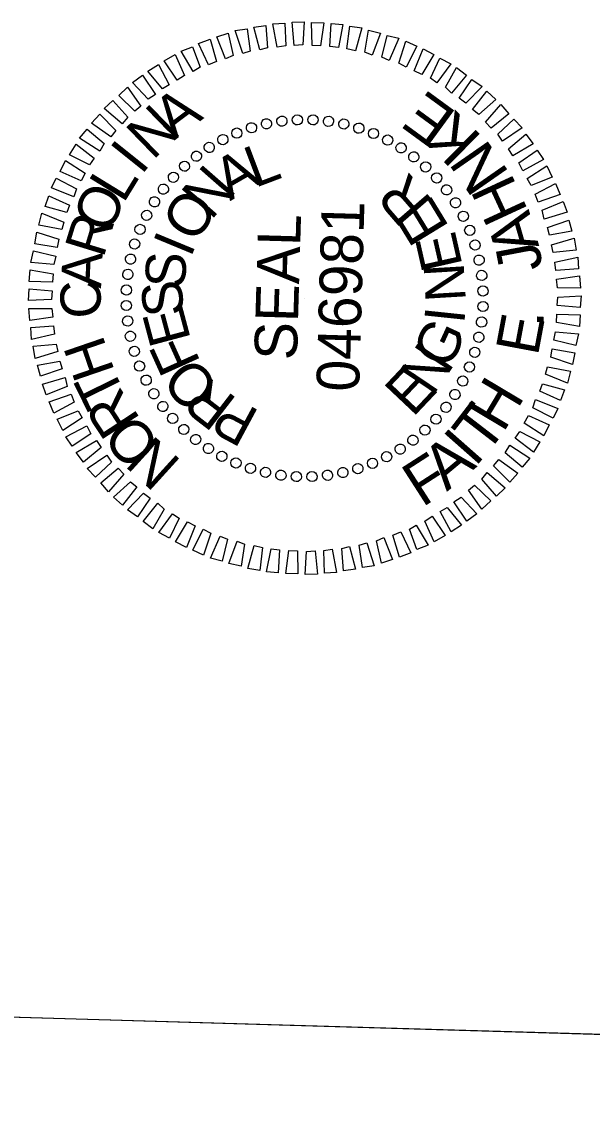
# Model space of a CAD drawing. Extents: x 2097002 to 2098146, y 685127 to 687089.
# Drawn here: x 2097162.3 to 2097242.5, y 686598.1 to 686752 of the extents above; entities that cross this region are included whole.
import ezdxf

# ---------------------------------------------------------------- set-up
doc = ezdxf.new("R2010")
doc.units = 0
for name, color, linetype in [('Default', 7, 'Continuous'), ('Sheet Layout Plan Border', 7, 'Continuous'), ('Sheet Title CELL', 7, 'Continuous')]:
    doc.layers.add(name, color=color, linetype=linetype)

msp = doc.modelspace()

# ---------------------------------------------------------------- linework, layer by layer
at = {"layer": 'Default'}
for p, q in [((2097194.58, 686737.11), (2097194.58, 686737.11)), ((2097196.69, 686737.65), (2097196.69, 686737.65)), ((2097198.9, 686737.99), (2097198.9, 686737.99)), ((2097201.06, 686738.23), (2097201.06, 686738.23)), ((2097203.26, 686738.21), (2097203.26, 686738.21)), ((2097205.46, 686738), (2097205.46, 686738)), ((2097207.59, 686737.59), (2097207.59, 686737.59)), ((2097209.68, 686737.08), (2097209.68, 686737.08)), ((2097190.58, 686735.43), (2097190.58, 686735.43)), ((2097192.55, 686736.37), (2097192.55, 686736.37)), ((2097211.76, 686736.31), (2097211.76, 686736.31)), ((2097213.73, 686735.36), (2097213.73, 686735.36)), ((2097188.64, 686734.34), (2097188.64, 686734.34)), ((2097215.65, 686734.3), (2097215.65, 686734.3)), ((2097186.86, 686733.14), (2097186.86, 686733.14)), ((2097217.42, 686733), (2097217.42, 686733)), ((2097185.16, 686731.69), (2097185.16, 686731.69)), ((2097219.13, 686731.6), (2097219.13, 686731.6)), ((2097183.62, 686730.18), (2097183.62, 686730.18)), ((2097220.63, 686730.05), (2097220.63, 686730.05)), ((2097182.22, 686728.47), (2097182.22, 686728.47)), ((2097222.08, 686728.36), (2097222.08, 686728.36)), ((2097180.92, 686726.71), (2097180.92, 686726.71)), ((2097223.28, 686726.58), (2097223.28, 686726.58)), ((2097179.86, 686724.79), (2097179.86, 686724.79)), ((2097224.38, 686724.64), (2097224.38, 686724.64)), ((2097178.9, 686722.81), (2097178.9, 686722.81)), ((2097225.32, 686722.66), (2097225.32, 686722.66)), ((2097178.14, 686720.73), (2097178.14, 686720.73)), ((2097226.06, 686720.64), (2097226.06, 686720.64)), ((2097177.63, 686718.65), (2097177.63, 686718.65)), ((2097226.6, 686718.53), (2097226.6, 686718.53)), ((2097177.22, 686716.51), (2097177.22, 686716.51)), ((2097226.93, 686716.31), (2097226.93, 686716.31)), ((2097177.01, 686714.31), (2097177.01, 686714.31)), ((2097227.17, 686714.16), (2097227.17, 686714.16)), ((2097202.08, 686713.14), (2097202.08, 686713.14)), ((2097176.99, 686712.11), (2097176.99, 686712.11)), ((2097227.16, 686711.96), (2097227.16, 686711.96)), ((2097177.23, 686709.96), (2097177.23, 686709.96)), ((2097226.94, 686709.76), (2097226.94, 686709.76)), ((2097177.57, 686707.75), (2097177.57, 686707.75)), ((2097226.53, 686707.62), (2097226.53, 686707.62)), ((2097178.1, 686705.63), (2097178.1, 686705.63)), ((2097226.02, 686705.54), (2097226.02, 686705.54)), ((2097178.85, 686703.61), (2097178.85, 686703.61)), ((2097225.26, 686703.46), (2097225.26, 686703.46)), ((2097179.79, 686701.63), (2097179.79, 686701.63)), ((2097224.3, 686701.49), (2097224.3, 686701.49)), ((2097180.88, 686699.7), (2097180.88, 686699.7)), ((2097223.25, 686699.57), (2097223.25, 686699.57)), ((2097182.08, 686697.91), (2097182.08, 686697.91)), ((2097221.94, 686697.8), (2097221.94, 686697.8)), ((2097183.53, 686696.22), (2097183.53, 686696.22)), ((2097220.54, 686696.09), (2097220.54, 686696.09)), ((2097185.04, 686694.67), (2097185.04, 686694.67)), ((2097219, 686694.59), (2097219, 686694.59)), ((2097186.75, 686693.27), (2097186.75, 686693.27)), ((2097217.31, 686693.13), (2097217.31, 686693.13)), ((2097188.51, 686691.97), (2097188.51, 686691.97)), ((2097190.43, 686690.91), (2097190.43, 686690.91)), ((2097213.59, 686690.84), (2097213.59, 686690.84)), ((2097215.52, 686691.94), (2097215.52, 686691.94)), ((2097192.4, 686689.96), (2097192.4, 686689.96)), ((2097194.48, 686689.2), (2097194.48, 686689.2)), ((2097209.59, 686689.16), (2097209.59, 686689.16)), ((2097211.61, 686689.9), (2097211.61, 686689.9)), ((2097196.57, 686688.69), (2097196.57, 686688.69)), ((2097198.71, 686688.27), (2097198.71, 686688.27)), ((2097200.9, 686688.06), (2097200.9, 686688.06)), ((2097203.1, 686688.05), (2097203.1, 686688.05)), ((2097205.26, 686688.28), (2097205.26, 686688.28)), ((2097207.47, 686688.62), (2097207.47, 686688.62))]:
    msp.add_line(p, q, dxfattribs=at)
for points in [[(2097193.38, 686747.5), (2097192.32, 686750.74), (2097193.98, 686750.99), (2097194.44, 686747.82)], [(2097195.79, 686748.03), (2097194.94, 686751.21), (2097196.64, 686751.46), (2097196.85, 686748.3)], [(2097198.21, 686748.41), (2097197.6, 686751.68), (2097199.3, 686751.78), (2097199.41, 686748.58)], [(2097200.61, 686748.64), (2097200.31, 686751.9), (2097202.01, 686751.95), (2097201.82, 686748.71)], [(2097203.11, 686748.62), (2097203.06, 686751.87), (2097204.76, 686751.82), (2097204.31, 686748.59)], [(2097205.61, 686748.5), (2097205.81, 686751.74), (2097207.45, 686751.6), (2097206.81, 686748.36)], [(2097208, 686748.18), (2097208.4, 686751.37), (2097210.09, 686751.12), (2097209.2, 686747.89)], [(2097210.54, 686747.7), (2097211.03, 686750.79), (2097212.72, 686750.39), (2097211.58, 686747.27)], [(2097188.58, 686745.94), (2097187.17, 686748.93), (2097188.78, 686749.54), (2097189.69, 686746.41)], [(2097190.95, 686746.77), (2097189.74, 686749.86), (2097191.31, 686750.36), (2097192.02, 686747.24)], [(2097212.92, 686746.99), (2097213.66, 686750.06), (2097215.3, 686749.67), (2097213.96, 686746.55)], [(2097215.3, 686746.17), (2097216.29, 686749.24), (2097217.82, 686748.54), (2097216.33, 686745.59)], [(2097186.4, 686745), (2097184.73, 686747.85), (2097186.3, 686748.46), (2097187.37, 686745.58)], [(2097217.47, 686745.1), (2097218.71, 686748.17), (2097220.23, 686747.37), (2097218.55, 686744.57)], [(2097184.16, 686743.77), (2097182.34, 686746.47), (2097183.87, 686747.38), (2097185.18, 686744.44)], [(2097219.74, 686744.04), (2097221.07, 686746.85), (2097222.6, 686746.05), (2097220.67, 686743.41)], [(2097182.08, 686742.53), (2097180.05, 686745.04), (2097181.53, 686745.95), (2097183.04, 686743.1)], [(2097221.85, 686742.77), (2097223.43, 686745.53), (2097224.8, 686744.49), (2097222.73, 686741.95)], [(2097180.09, 686741.09), (2097177.9, 686743.45), (2097179.28, 686744.46), (2097181.1, 686741.76)], [(2097223.81, 686741.22), (2097225.58, 686743.87), (2097227.01, 686742.87), (2097224.74, 686740.54)], [(2097178.23, 686739.39), (2097175.95, 686741.61), (2097177.18, 686742.77), (2097179.06, 686740.12)], [(2097225.66, 686739.66), (2097227.69, 686742.2), (2097228.96, 686741.07), (2097226.54, 686738.94)], [(2097176.43, 686737.64), (2097173.89, 686739.77), (2097175.13, 686740.93), (2097177.21, 686738.57)], [(2097227.51, 686737.86), (2097229.63, 686740.35), (2097230.75, 686739.06), (2097228.29, 686737.03)], [(2097174.83, 686735.79), (2097172.13, 686737.72), (2097173.27, 686738.98), (2097175.56, 686736.72)], [(2097173.27, 686733.78), (2097170.42, 686735.62), (2097171.51, 686736.88), (2097173.9, 686734.86)], [(2097229.21, 686736.16), (2097231.48, 686738.29), (2097232.64, 686737.06), (2097229.88, 686735.19)], [(2097230.7, 686734.11), (2097233.17, 686736.19), (2097234.18, 686734.81), (2097231.33, 686733.14)], [(2097171.86, 686731.87), (2097169.05, 686733.3), (2097169.95, 686734.78), (2097172.49, 686732.8)], [(2097232.15, 686732.17), (2097234.75, 686733.95), (2097235.66, 686732.62), (2097232.72, 686731.05)], [(2097170.65, 686729.61), (2097167.73, 686730.94), (2097168.48, 686732.47), (2097171.23, 686730.69)], [(2097233.33, 686729.93), (2097236.09, 686731.71), (2097236.84, 686730.13), (2097233.91, 686728.97)], [(2097169.63, 686727.38), (2097166.52, 686728.63), (2097167.16, 686730.01), (2097170.02, 686728.52)], [(2097234.47, 686727.75), (2097237.32, 686729.27), (2097237.97, 686727.7), (2097234.89, 686726.64)], [(2097168.67, 686725.16), (2097165.59, 686726), (2097166.14, 686727.54), (2097169.05, 686726.2)], [(2097235.46, 686725.52), (2097238.39, 686726.74), (2097238.95, 686725.22), (2097235.72, 686724.26)], [(2097167.95, 686722.78), (2097164.71, 686723.38), (2097165.16, 686725.06), (2097168.23, 686723.82)], [(2097236.18, 686723.05), (2097239.22, 686724.11), (2097239.62, 686722.55), (2097236.5, 686721.99)], [(2097167.32, 686720.25), (2097164.14, 686720.79), (2097164.44, 686722.43), (2097167.51, 686721.44)], [(2097236.76, 686720.63), (2097239.94, 686721.59), (2097240.24, 686719.88), (2097236.98, 686719.57)], [(2097166.85, 686717.86), (2097163.61, 686718.16), (2097163.96, 686719.8), (2097167.09, 686719.06)], [(2097237.24, 686718.22), (2097240.47, 686718.92), (2097240.57, 686717.27), (2097237.36, 686717.01)], [(2097166.63, 686715.37), (2097163.38, 686715.46), (2097163.48, 686717.11), (2097166.72, 686716.56)], [(2097237.47, 686715.81), (2097240.69, 686716.27), (2097240.84, 686714.56), (2097237.59, 686714.6)], [(2097166.51, 686712.97), (2097163.26, 686712.81), (2097163.35, 686714.46), (2097166.6, 686714.17)], [(2097237.65, 686713.3), (2097240.91, 686713.46), (2097240.81, 686711.81), (2097237.57, 686712.1)], [(2097166.69, 686710.46), (2097163.47, 686710.01), (2097163.32, 686711.71), (2097166.57, 686711.67)], [(2097237.53, 686710.9), (2097240.78, 686710.81), (2097240.68, 686709.16), (2097237.45, 686709.71)], [(2097166.92, 686708.06), (2097163.7, 686707.35), (2097163.6, 686709), (2097166.8, 686709.26)], [(2097237.31, 686708.41), (2097240.55, 686708.12), (2097240.2, 686706.48), (2097237.07, 686707.22)], [(2097167.4, 686705.64), (2097164.22, 686704.68), (2097163.92, 686706.39), (2097167.18, 686706.7)], [(2097236.84, 686706.02), (2097240.03, 686705.48), (2097239.73, 686703.84), (2097236.66, 686704.83)], [(2097167.98, 686703.22), (2097164.95, 686702.16), (2097164.54, 686703.72), (2097167.66, 686704.28)], [(2097236.22, 686703.49), (2097239.45, 686702.9), (2097239, 686701.21), (2097235.94, 686702.45)], [(2097168.71, 686700.75), (2097165.77, 686699.54), (2097165.22, 686701.05), (2097168.44, 686702.01)], [(2097235.5, 686701.11), (2097238.57, 686700.27), (2097238.03, 686698.74), (2097235.12, 686700.07)], [(2097169.69, 686698.52), (2097166.85, 686697), (2097166.19, 686698.57), (2097169.28, 686699.63)], [(2097234.53, 686698.89), (2097237.65, 686697.65), (2097237.01, 686696.26), (2097234.15, 686697.75)], [(2097170.83, 686696.34), (2097168.08, 686694.57), (2097167.32, 686696.14), (2097170.26, 686697.3)], [(2097233.52, 686696.67), (2097236.43, 686695.33), (2097235.68, 686693.8), (2097232.94, 686695.58)], [(2097172.02, 686694.1), (2097169.41, 686692.33), (2097168.5, 686693.65), (2097171.45, 686695.22)], [(2097232.3, 686694.4), (2097235.11, 686692.97), (2097234.22, 686691.49), (2097231.67, 686693.47)], [(2097173.46, 686692.16), (2097171, 686690.08), (2097169.99, 686691.46), (2097172.84, 686693.13)], [(2097230.89, 686692.49), (2097233.74, 686690.66), (2097232.65, 686689.39), (2097230.26, 686691.41)], [(2097174.95, 686690.11), (2097172.69, 686687.98), (2097171.52, 686689.21), (2097174.28, 686691.08)], [(2097176.65, 686688.41), (2097174.53, 686685.92), (2097173.42, 686687.21), (2097175.88, 686689.24)], [(2097229.34, 686690.48), (2097232.03, 686688.56), (2097230.89, 686687.29), (2097228.61, 686689.56)], [(2097227.73, 686688.63), (2097230.27, 686686.51), (2097229.04, 686685.34), (2097226.95, 686687.7)], [(2097178.5, 686686.61), (2097176.48, 686684.07), (2097175.21, 686685.2), (2097177.62, 686687.34)], [(2097225.93, 686686.88), (2097228.22, 686684.66), (2097226.98, 686683.5), (2097225.11, 686686.16)], [(2097180.36, 686685.06), (2097178.58, 686682.41), (2097177.16, 686683.4), (2097179.43, 686685.73)], [(2097224.08, 686685.18), (2097226.26, 686682.82), (2097224.88, 686681.81), (2097223.06, 686684.51)], [(2097182.31, 686683.5), (2097180.73, 686680.74), (2097179.36, 686681.78), (2097181.44, 686684.32)], [(2097222.09, 686683.74), (2097224.11, 686681.23), (2097222.64, 686680.32), (2097221.12, 686683.17)], [(2097184.43, 686682.24), (2097183.09, 686679.42), (2097181.57, 686680.22), (2097183.49, 686682.86)], [(2097186.7, 686681.17), (2097185.46, 686678.1), (2097183.93, 686678.9), (2097185.61, 686681.7)], [(2097220, 686682.5), (2097221.82, 686679.8), (2097220.29, 686678.89), (2097218.98, 686681.83)], [(2097188.87, 686680.11), (2097187.88, 686677.03), (2097186.35, 686677.73), (2097187.83, 686680.69)], [(2097215.58, 686680.33), (2097217, 686677.34), (2097215.38, 686676.73), (2097214.47, 686679.86)], [(2097217.76, 686681.27), (2097219.43, 686678.42), (2097217.86, 686677.81), (2097216.8, 686680.69)], [(2097191.24, 686679.29), (2097190.5, 686676.21), (2097188.86, 686676.6), (2097190.21, 686679.72)], [(2097193.62, 686678.57), (2097193.13, 686675.48), (2097191.44, 686675.88), (2097192.59, 686679)], [(2097210.79, 686678.77), (2097211.84, 686675.54), (2097210.19, 686675.28), (2097209.73, 686678.45)], [(2097213.21, 686679.5), (2097214.42, 686676.41), (2097212.85, 686675.91), (2097212.15, 686679.03)], [(2097196.16, 686678.09), (2097195.77, 686674.9), (2097194.07, 686675.15), (2097194.97, 686678.38)], [(2097198.55, 686677.77), (2097198.36, 686674.53), (2097196.71, 686674.68), (2097197.36, 686677.91)], [(2097201.05, 686677.65), (2097201.11, 686674.4), (2097199.41, 686674.45), (2097199.85, 686677.69)], [(2097203.55, 686677.63), (2097203.86, 686674.37), (2097202.15, 686674.32), (2097202.35, 686677.56)], [(2097205.96, 686677.86), (2097206.56, 686674.59), (2097204.86, 686674.49), (2097204.75, 686677.69)], [(2097208.37, 686678.24), (2097209.23, 686675.06), (2097207.52, 686674.81), (2097207.31, 686677.97)]]:
    msp.add_lwpolyline(points, close=True, dxfattribs=at)
for centre, major_axis in [((2097196.72, 686737.64), (-0.154, 0.703)), ((2097198.88, 686738.01), (-0.092, 0.714)), ((2097201.06, 686738.19), (-0.029, 0.719)), ((2097203.25, 686738.19), (0.033, 0.719)), ((2097205.43, 686737.99), (0.096, 0.714)), ((2097207.58, 686737.61), (0.158, 0.702)), ((2097192.55, 686736.33), (-0.274, 0.666)), ((2097194.61, 686737.08), (-0.215, 0.687)), ((2097209.69, 686737.03), (0.218, 0.686)), ((2097211.75, 686736.28), (0.277, 0.664)), ((2097190.57, 686735.42), (-0.331, 0.64)), ((2097213.73, 686735.35), (0.334, 0.638)), ((2097186.87, 686733.08), (-0.437, 0.572)), ((2097188.67, 686734.33), (-0.385, 0.608)), ((2097215.62, 686734.25), (0.389, 0.606)), ((2097217.41, 686732.99), (0.44, 0.57)), ((2097185.19, 686731.68), (-0.485, 0.532)), ((2097219.08, 686731.58), (0.488, 0.529)), ((2097183.64, 686730.13), (-0.529, 0.488)), ((2097220.62, 686730.03), (0.532, 0.485)), ((2097182.23, 686728.46), (-0.57, 0.44)), ((2097222.02, 686728.35), (0.572, 0.437)), ((2097180.97, 686726.67), (-0.606, 0.389)), ((2097223.27, 686726.55), (0.608, 0.385)), ((2097179.87, 686724.78), (-0.638, 0.334)), ((2097224.36, 686724.65), (0.64, 0.331)), ((2097178.94, 686722.8), (-0.664, 0.277)), ((2097225.28, 686722.67), (0.666, 0.274)), ((2097178.18, 686720.75), (-0.686, 0.218)), ((2097226.02, 686720.61), (0.687, 0.215)), ((2097177.61, 686718.63), (-0.702, 0.158)), ((2097226.58, 686718.49), (0.703, 0.154)), ((2097177.23, 686716.48), (-0.714, 0.096)), ((2097226.96, 686716.34), (0.714, 0.092)), ((2097177.03, 686714.3), (-0.719, 0.033)), ((2097227.14, 686714.16), (0.719, 0.029)), ((2097177.02, 686712.11), (-0.719, -0.029)), ((2097227.13, 686711.97), (0.719, -0.033)), ((2097177.21, 686709.93), (-0.714, -0.092)), ((2097226.94, 686709.79), (0.714, -0.096)), ((2097177.58, 686707.78), (-0.703, -0.154)), ((2097226.55, 686707.64), (0.702, -0.158)), ((2097178.14, 686705.66), (-0.687, -0.215)), ((2097225.98, 686705.53), (0.686, -0.218)), ((2097178.88, 686703.6), (-0.666, -0.274)), ((2097225.23, 686703.47), (0.664, -0.277)), ((2097179.8, 686701.62), (-0.64, -0.331)), ((2097224.29, 686701.49), (0.638, -0.334)), ((2097180.89, 686699.72), (-0.608, -0.385)), ((2097223.2, 686699.6), (0.606, -0.389)), ((2097182.14, 686697.93), (-0.572, -0.437)), ((2097221.94, 686697.81), (0.57, -0.44)), ((2097183.54, 686696.25), (-0.532, -0.485)), ((2097220.52, 686696.14), (0.529, -0.488)), ((2097185.09, 686694.69), (-0.488, -0.529)), ((2097218.97, 686694.6), (0.485, -0.532)), ((2097186.76, 686693.28), (-0.44, -0.57)), ((2097217.29, 686693.19), (0.437, -0.572)), ((2097188.55, 686692.02), (-0.389, -0.606)), ((2097215.5, 686691.94), (0.385, -0.608)), ((2097190.44, 686690.92), (-0.334, -0.638)), ((2097192.42, 686689.99), (-0.277, -0.664)), ((2097211.61, 686689.94), (0.274, -0.666)), ((2097213.6, 686690.86), (0.331, -0.64)), ((2097194.47, 686689.24), (-0.218, -0.686)), ((2097196.58, 686688.67), (-0.158, -0.702)), ((2097207.44, 686688.63), (0.154, -0.703)), ((2097209.55, 686689.19), (0.215, -0.687)), ((2097198.74, 686688.28), (-0.096, -0.714)), ((2097200.92, 686688.08), (-0.033, -0.719)), ((2097203.1, 686688.08), (0.029, -0.719)), ((2097205.28, 686688.26), (0.092, -0.714))]:
    msp.add_ellipse(centre, major_axis=major_axis, ratio=0.999708, dxfattribs=at)
at = {"layer": 'Sheet Layout Plan Border'}
msp.add_lwpolyline([(2098110.68, 686386.52), (2098090.85, 685704.42), (2097236.93, 685318.96), (2097029.37, 685324.99), (2097061.33, 686424.42), (2097062.77, 686473.85), (2097066.87, 686614.87), (2097306.86, 686607.89), (2097310.43, 686730.69), (2098032.53, 686709.7), (2098023.21, 686389.06)], close=True, dxfattribs=at)
at = {"layer": 'Sheet Title CELL'}
msp.add_line((2097066.87, 686614.87), (2097256.01, 686609.37), dxfattribs=at)

# ---------------------------------------------------------------- texts
at = {"layer": 'Default'}
for s, height, rotation, p in [('A', 5.95, 36.952, (2097183.77, 686735.28)), ('E', 6.29, 143.8279, (2097223.64, 686739.12)), ('N', 5.99, 44.1537, (2097180.73, 686732.41)), ('K', 6.36, 135.5439, (2097227.16, 686735.75)), ('I', 5.98, 51.355, (2097179.12, 686730.31)), ('L', 5.79, 20.7357, (2097195.08, 686728.6)), ('N', 6.36, 124.8181, (2097230.93, 686730.68)), ('A', 5.89, 30.0951, (2097191.57, 686726.75)), ('N', 5.99, 48.8114, (2097188.89, 686723.97)), ('R', 5.99, 130.8162, (2097220.23, 686726.71)), ('L', 5.93, 58.5557, (2097176.6, 686726.33)), ('H', 6.27, 114.8341, (2097233.53, 686725.42)), ('O', 5.85, 65.756, (2097174.63, 686721.99)), ('O', 5.94, 58.1683, (2097186.79, 686720.68)), ('046981', 5.998, 88.3348, (2097209.71, 686699.94)), ('E', 5.96, 121.4589, (2097222.48, 686723.1)), ('R', 5.75, 72.9559, (2097173.78, 686718.66)), ('SEAL', 5.998, 88.3348, (2097200.98, 686704.37)), ('A', 6.15, 105.9938, (2097235.05, 686720.44)), ('I', 5.83, 67.5244, (2097186.04, 686718.7)), ('E', 5.74, 102.7466, (2097224.28, 686717.74)), ('J', 6.08, 100.736, (2097235.58, 686717.39)), ('A', 5.64, 87.3551, (2097173.46, 686714.47)), ('S', 5.64, 86.2352, (2097185.21, 686714.43)), ('N', 5.65, 93.3912, (2097224.73, 686712.78)), ('C', 5.66, 94.5547, (2097173.64, 686710.51)), ('S', 5.67, 95.5904, (2097185.16, 686710.83)), ('E', 5.77, 104.9459, (2097186.11, 686707.35)), ('I', 5.65, 84.036, (2097224.48, 686709.43)), ('E', 6.04, 79.3925, (2097234.83, 686704.9)), ('G', 5.86, 65.3251, (2097222.39, 686702.94)), ('.', 6, 86.5019, (2097235.59, 686709.02)), ('H', 5.82, 108.9543, (2097175.42, 686702.86)), ('F', 5.89, 114.3019, (2097187.51, 686704.11)), ('N', 5.95, 55.9688, (2097220.03, 686699.21)), ('O', 5.98, 133.0161, (2097190.37, 686700.72)), ('E', 5.99, 46.6117, (2097217.25, 686696.29)), ('T', 5.91, 116.1546, (2097176.98, 686699.56)), ('R', 5.93, 142.3745, (2097192.76, 686698.9)), ('H', 6.3, 59.2082, (2097229.98, 686694.11)), ('R', 5.97, 123.3553, (2097179.08, 686696.1)), ('T', 6.36, 52.4079, (2097227.53, 686690.94)), ('P', 5.84, 151.7337, (2097195.92, 686697.21)), ('O', 5.99, 130.5566, (2097182.08, 686692.56)), ('I', 6.37, 48.606, (2097226, 686689.3)), ('N', 5.96, 137.7583, (2097184.91, 686690.18)), ('A', 6.35, 39.7657, (2097222.05, 686685.91)), ('F', 6.29, 32.7491, (2097218.58, 686683.68))]:
    msp.add_text(s, height=height, rotation=rotation, dxfattribs=at).set_placement(p)

doc.saveas('drawing.dxf')
